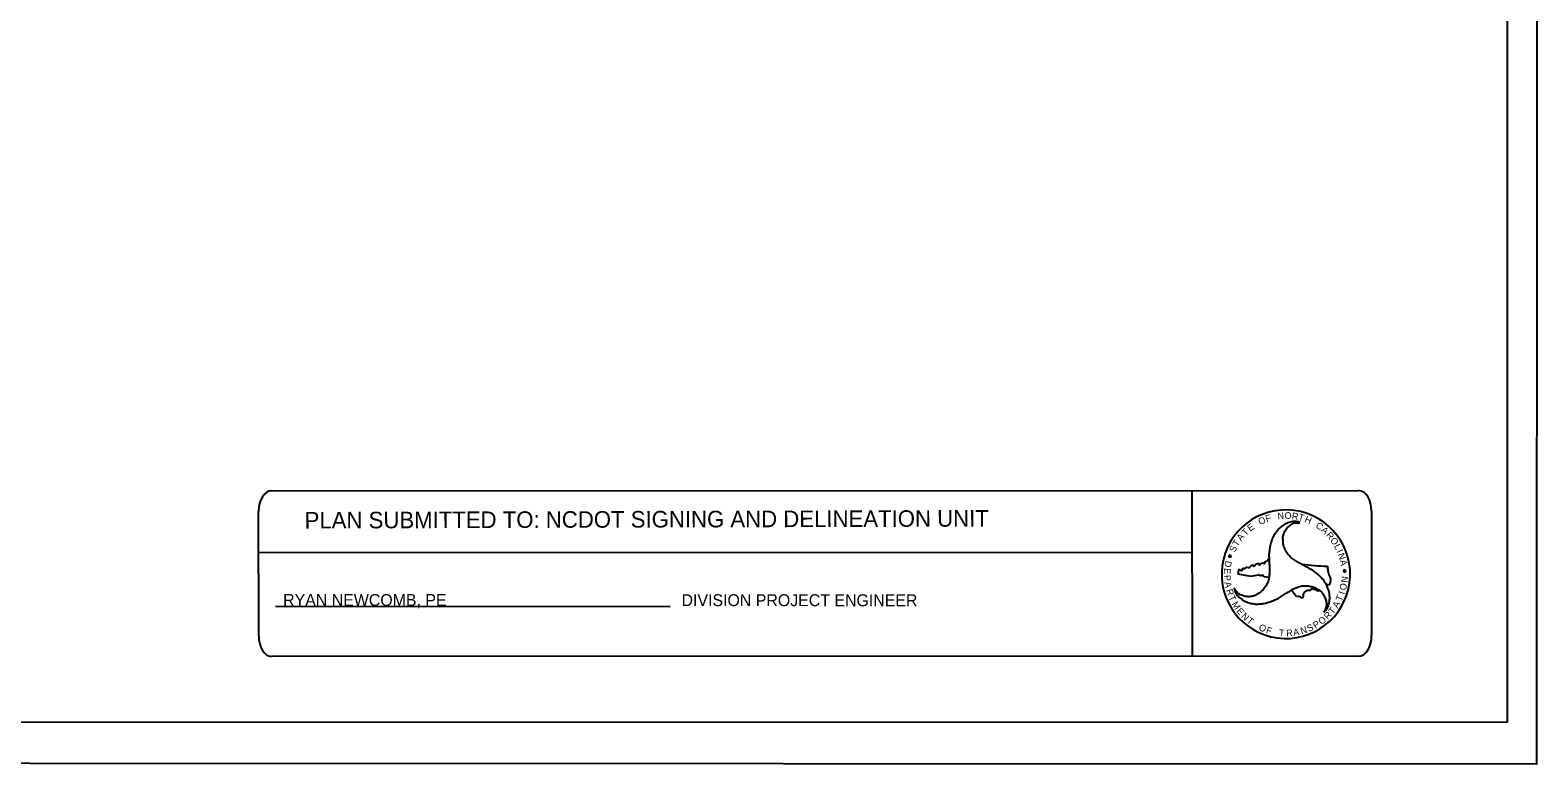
# Model space of a CAD drawing. Extents: x 50667 to 52386, y 46650 to 50479.
# Drawn here: x 51544 to 52386, y 49383 to 49792 of the extents above; entities that cross this region are included whole.
import ezdxf

# ---------------------------------------------------------------- set-up
doc = ezdxf.new("R2010")
doc.units = 0
for name, color, linetype in [('Default', 7, 'Continuous'), ('DEV TUBULAR MARKER SECTIONAL VIEW CELL', 7, 'Continuous'), ('Exist Utilities Power Pole Text Tag Number', 7, 'Continuous'), ('TSCONFLICT', 7, 'Continuous')]:
    doc.layers.add(name, color=color, linetype=linetype)

msp = doc.modelspace()

# ---------------------------------------------------------------- linework, layer by layer
at = {"layer": 'Default'}
for p, q in [((51679.08, 49534.82), (52286, 49535)), ((52192.94, 49534.97), (52192.98, 49442.62)), ((51671.91, 49454.01), (51671.88, 49523.38)), ((52293.2, 49523.51), (52293.23, 49454.15)), ((51671.87, 49500.47), (52192.95, 49500.75)), ((51681.34, 49470.48), (51901.65, 49470.38)), ((52286.03, 49442.65), (51679.11, 49442.47))]:
    msp.add_line(p, q, dxfattribs=at)
for centre, major_axis, start_param, end_param in [((51679.08, 49523.39), (0, 11.49), 0.000702, 1.571498), ((52286.01, 49523.51), (0, 11.49), 4.713091, 6.283887), ((51679.11, 49454.02), (0, -11.49), 4.713091, 6.283887), ((52286.03, 49454.14), (0, -11.49), 0.000702, 1.571498)]:
    msp.add_ellipse(centre, major_axis=major_axis, ratio=0.62659, start_param=start_param, end_param=end_param, dxfattribs=at)
at = {"layer": 'DEV TUBULAR MARKER SECTIONAL VIEW CELL'}
msp.add_lwpolyline([(52369.04, 50455.98), (50869.05, 50455.87), (50869.12, 49405.87), (52369.12, 49405.98)], close=True, dxfattribs=at)
at = {"layer": 'Exist Utilities Power Pole Text Tag Number'}
msp.add_lwpolyline([(52386.04, 50478.48), (50703.13, 50479.27), (50702.62, 49383.36), (52385.53, 49382.58)], close=True, dxfattribs=at)
at = {"layer": 'TSCONFLICT'}
for p, q in [((52253.24, 49517.26), (52253.17, 49517.19)), ((52253.24, 49517.26), (52253.17, 49517.19)), ((52213.81, 49498.37), (52213.34, 49498.82)), ((52213.34, 49498.82), (52213.99, 49498.73)), ((52213.54, 49497.78), (52213.81, 49498.37)), ((52214.08, 49498.09), (52213.54, 49497.78)), ((52213.99, 49498.73), (52214.25, 49499.3)), ((52214.56, 49497.64), (52214.08, 49498.09)), ((52214.25, 49499.3), (52214.39, 49498.68)), ((52214.39, 49498.68), (52215.02, 49498.6)), ((52215.02, 49498.6), (52214.45, 49498.28)), ((52214.45, 49498.28), (52214.56, 49497.64)), ((52254.18, 49493.94), (52254.18, 49493.94)), ((52218.78, 49488.37), (52219.16, 49490.59)), ((52225.79, 49487.17), (52218.78, 49488.37)), ((52229.98, 49487.82), (52225.79, 49487.17)), ((52235.96, 49486.52), (52233.02, 49486.95)), ((52277.96, 49490.44), (52277.32, 49490.53)), ((52277.32, 49490.53), (52277.8, 49490.08)), ((52277.8, 49490.08), (52277.53, 49489.49)), ((52277.53, 49489.49), (52278.07, 49489.8)), ((52278.23, 49491.01), (52277.96, 49490.44)), ((52278.07, 49489.8), (52278.54, 49489.36)), ((52278.38, 49490.39), (52278.23, 49491.01)), ((52279.01, 49490.33), (52278.38, 49490.39)), ((52278.44, 49490), (52279.01, 49490.33)), ((52278.54, 49489.36), (52278.44, 49490)), ((52251.22, 49475.73), (52248.56, 49479.52)), ((52248.56, 49479.52), (52248.56, 49479.52))]:
    msp.add_line(p, q, dxfattribs=at)
for centre, radius, start, end in [((52245.4, 49488.38), 35.88, 352.42777, 172.42777), ((52245.4, 49488.38), 35.88, 172.42777, 352.42777), ((52276.37, 49690.1), 197.41, 258.10627, 258.20586), ((52276.37, 49690.1), 197.41, 263.54532, 267.75133)]:
    msp.add_arc(centre, radius, start, end, dxfattribs=at)
for points in [[(52253.17, 49517.19), (52252.36, 49517.52), (52249.88, 49517.75), (52247.27, 49517.28), (52247.03, 49517.19), (52245.69, 49516.7), (52244.23, 49515.89), (52241.96, 49514.25), (52240.11, 49512.11), (52239.36, 49511.19), (52238.74, 49510.02), (52237.57, 49507.51), (52236.81, 49505.04), (52236.25, 49502.1), (52235.95, 49499.5), (52236.02, 49496.79), (52236.13, 49494.06), (52236.17, 49491.41), (52236.18, 49488.69), (52235.84, 49486.03), (52235.79, 49485.8), (52234.94, 49483.04), (52233.47, 49480.72), (52231.72, 49478.83), (52230.72, 49477.99), (52229.35, 49477.19), (52228.57, 49476.72), (52226.78, 49476.09), (52224.16, 49475.83), (52221.69, 49476.3), (52219.56, 49477.16), (52217.79, 49478.66), (52216.5, 49480.64)], [(52266.51, 49467.18), (52267.16, 49467.7), (52268.62, 49469.73), (52269.52, 49472.23), (52269.59, 49472.48), (52269.8, 49473.89), (52269.83, 49475.58), (52269.58, 49478.36), (52268.62, 49481.02), (52268.22, 49482.13), (52267.5, 49483.27), (52265.92, 49485.53), (52264.17, 49487.43), (52261.89, 49489.37), (52259.78, 49490.91), (52257.39, 49492.24), (52254.99, 49493.5), (52252.69, 49494.78), (52250.29, 49496.15), (52248.19, 49497.76), (52248.02, 49497.93), (52246.02, 49500.05), (52244.75, 49502.49), (52243.98, 49504.94), (52243.79, 49506.2), (52243.78, 49507.81), (52243.73, 49508.73), (52244.11, 49510.58), (52245.2, 49513), (52246.82, 49514.88), (52248.63, 49516.28), (52250.83, 49517.07), (52253.17, 49517.19), (52253.24, 49517.26)], [(52219.16, 49490.59), (52219.11, 49490.81), (52219.51, 49491), (52220.5, 49490.43), (52221.09, 49490.82), (52221.13, 49491.27), (52221.6, 49491.67), (52222.3, 49491.43), (52223.06, 49492.17), (52223.67, 49492.23), (52224.93, 49492.06), (52226.61, 49493.36), (52227.25, 49493.37), (52227.35, 49492.95), (52227.73, 49492.82), (52228.53, 49493.97), (52228.72, 49494.12), (52229.94, 49494.43), (52230.22, 49494.17), (52230.24, 49493.61), (52230.39, 49493.48), (52230.81, 49493.7), (52231.41, 49494.29), (52232.44, 49494.66), (52233.51, 49494.38), (52233.81, 49495.25), (52235.2, 49495.94), (52235.54, 49496.42), (52235.67, 49496.94)], [(52236.02, 49496.86), (52236.02, 49496.79), (52236.13, 49494.06), (52236.17, 49491.41), (52236.18, 49488.69), (52235.95, 49486.52)], [(52268, 49482.56), (52267.5, 49483.27), (52265.92, 49485.53), (52264.17, 49487.43), (52261.89, 49489.37), (52259.78, 49490.91), (52257.39, 49492.24), (52254.99, 49493.5), (52254.18, 49493.94)], [(52268.62, 49492.84), (52268.82, 49490.29), (52269.73, 49487.2), (52270.36, 49485.5), (52270.15, 49484.13), (52269.62, 49482.53), (52268.01, 49482.57)], [(52233.02, 49486.95), (52232.81, 49487.52), (52232.26, 49487.76), (52231.43, 49487.46), (52230.86, 49487.57), (52230.28, 49488.12), (52229.98, 49487.82)], [(52216.5, 49480.64), (52216.65, 49479.77), (52217.68, 49477.51), (52219.38, 49475.47), (52219.58, 49475.33), (52220.7, 49474.39), (52222.13, 49473.55), (52224.68, 49472.38), (52227.44, 49471.88), (52228.61, 49471.67), (52229.99, 49471.73), (52232.69, 49471.98), (52235.2, 49472.53), (52238.05, 49473.53), (52240.42, 49474.56), (52242.76, 49475.99), (52245.06, 49477.46), (52247.35, 49478.81), (52249.71, 49480.16), (52252.17, 49481.21), (52252.43, 49481.28), (52255.25, 49481.93), (52257.97, 49481.82), (52260.45, 49481.26), (52261.72, 49480.81), (52263.06, 49480), (52263.91, 49479.58), (52265.32, 49478.33), (52266.84, 49476.19), (52267.67, 49473.84), (52267.99, 49471.55), (52267.57, 49469.26), (52266.51, 49467.18)], [(52248.56, 49479.52), (52249.71, 49480.16), (52252.17, 49481.21), (52252.43, 49481.28), (52255.25, 49481.93), (52257.97, 49481.82), (52260.45, 49481.26), (52261.72, 49480.81), (52263.06, 49480), (52263.84, 49479.6)], [(52263.83, 49479.59), (52263.4, 49478.99), (52262.84, 49479.02), (52261.96, 49479.93), (52260.73, 49479.85), (52260.22, 49480.24), (52259.86, 49480.3), (52258.85, 49479.33), (52257.62, 49479.22), (52255.51, 49478.06), (52255, 49477.28), (52254.91, 49475.48), (52254.39, 49475.19), (52253.83, 49475.36), (52252.7, 49475.98), (52251.22, 49475.73)]]:
    msp.add_spline(points, degree=3, dxfattribs=at)

# ---------------------------------------------------------------- texts
at = {"layer": 'Default'}
for s, height, rotation, p in [('PLAN SUBMITTED TO: NCDOT SIGNING AND DELINEATION UNIT', 9.2466, 0.1623, (51697.57, 49513.86)), ('RYAN NEWCOMB, PE', 6.6381, 359.97341, (51685.56, 49470.69)), ('DIVISION PROJECT ENGINEER', 6.6381, 359.97341, (51907.99, 49470.58))]:
    msp.add_text(s, height=height, rotation=rotation, dxfattribs=at).set_placement(p)
at = {"layer": 'TSCONFLICT'}
for s, height, rotation, p in [('O', 3.74, 24.64533, (52231, 49515.74)), ('F', 3.74, 17.49849, (52234.59, 49517.37)), ('N', 3.73, 5.41155, (52240.89, 49518.98)), ('O', 3.74, 357.91344, (52244.52, 49519.31)), ('R', 3.73, 351.30351, (52248.47, 49519.16)), ('T', 3.74, 344.65388, (52252, 49518.62)), ('H', 3.73, 337.56916, (52255.52, 49517.63)), ('A', 3.75, 50.75556, (52220.39, 49506.56)), ('T', 3.72, 43.70034, (52222.84, 49509.55)), ('E', 3.72, 36.58471, (52225.49, 49512.06)), ('C', 3.72, 325.22681, (52261.63, 49514.74)), ('A', 3.73, 317.72978, (52264.68, 49512.6)), ('R', 3.73, 311.36583, (52267.52, 49510.02)), ('S', 3.73, 64.18402, (52216.85, 49500.3)), ('T', 3.74, 57.80787, (52218.41, 49503.5)), ('O', 3.74, 304.24623, (52269.87, 49507.34)), ('L', 3.72, 298.01255, (52272.11, 49504.05)), ('I', 3.74, 294.02321, (52273.56, 49501.17)), ('D', 3.73, 260.28077, (52211.59, 49496.08)), ('N', 3.73, 288.32311, (52274.28, 49499.5)), ('A', 3.73, 280.89113, (52275.41, 49496.01)), ('E', 3.72, 266.56866, (52210.9, 49491.85)), ('P', 3.73, 274.10105, (52210.73, 49487.79)), ('N', 3.73, 84.6359, (52279.78, 49483.51)), ('A', 3.73, 280.69363, (52211.02, 49483.81)), ('R', 3.73, 287.76227, (52211.89, 49479.48)), ('T', 3.73, 294.4128, (52213.18, 49475.57)), ('T', 3.73, 66.60235, (52276.47, 49472.93)), ('I', 3.74, 72.25226, (52278.13, 49476.81)), ('O', 3.72, 77.38789, (52278.83, 49479.1)), ('M', 3.72, 301.64784, (52214.99, 49471.73)), ('E', 3.72, 309.11461, (52217.55, 49467.73)), ('R', 3.74, 45.3311, (52268.81, 49462.76)), ('T', 3.72, 51.43089, (52271.68, 49465.74)), ('A', 3.74, 59.51793, (52274.27, 49469.09)), ('N', 3.74, 316.08615, (52220.13, 49464.63)), ('T', 3.73, 322.92815, (52223.19, 49461.74)), ('O', 3.73, 336.23184, (52229.85, 49457.37)), ('F', 3.73, 343.39707, (52234.01, 49455.61)), ('N', 3.72, 17.04768, (52254.12, 49454.81)), ('S', 3.72, 24.25815, (52258.14, 49456.12)), ('P', 3.73, 31.45, (52261.89, 49457.84)), ('O', 3.74, 38.14199, (52265.28, 49459.95)), ('T', 3.72, 356.3063, (52241.45, 49453.91)), ('R', 3.74, 3.26292, (52245.67, 49453.68)), ('A', 3.72, 10.01605, (52249.79, 49453.97))]:
    msp.add_text(s, height=height, rotation=rotation, dxfattribs=at).set_placement(p)

doc.saveas('drawing.dxf')
